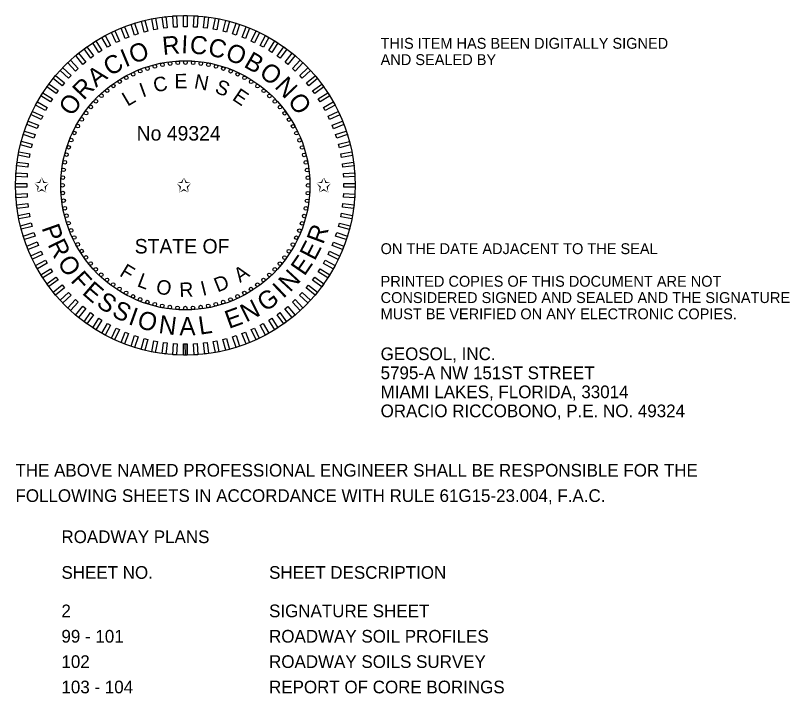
# Model space of a CAD drawing. Extents: x -816.9 to -790.1, y -2199.5 to -2188.9.
# Drawn here: x -794.327 to -790.055, y -2192.952 to -2189.209 of the extents above; entities that cross this region are included whole.
import ezdxf

# ---------------------------------------------------------------- set-up
doc = ezdxf.new("R2010")
doc.units = 0
for name, color, linetype in [('Logo_dp', 7, 'Continuous'), ('NonPlottingEle_dp', 7, 'Continuous'), ('TextMisc', 7, 'Continuous'), ('TextNotes', 7, 'Continuous')]:
    doc.layers.add(name, color=color, linetype=linetype)

msp = doc.modelspace()

# ---------------------------------------------------------------- linework, layer by layer
at = {"layer": 'Logo_dp'}
for p, q in [((-793.3999, -2191.0843), (-793.4001, -2191.0218)), ((-793.3899, -2191.0843), (-793.3901, -2191.0218)), ((-793.3799, -2191.0843), (-793.3801, -2191.0218))]:
    msp.add_line(p, q, dxfattribs=at)
for points in [[(-793.5976, -2189.2967), (-793.6172, -2189.3018), (-793.6327, -2189.2413), (-793.6132, -2189.2363)], [(-793.5438, -2189.2854), (-793.5637, -2189.2892), (-793.5754, -2189.2278), (-793.5555, -2189.224)], [(-793.4895, -2189.2774), (-793.5095, -2189.2799), (-793.5173, -2189.218), (-793.4973, -2189.2155)], [(-793.4347, -2189.2729), (-793.4548, -2189.2741), (-793.4587, -2189.2118), (-793.4386, -2189.2106)], [(-793.3797, -2189.2718), (-793.3999, -2189.2718), (-793.3999, -2189.2093), (-793.3797, -2189.2093)], [(-793.3248, -2189.2741), (-793.3449, -2189.2729), (-793.341, -2189.2106), (-793.3209, -2189.2118)], [(-793.2701, -2189.28), (-793.2901, -2189.2774), (-793.2823, -2189.2155), (-793.2623, -2189.218)], [(-793.2159, -2189.2892), (-793.2357, -2189.2854), (-793.224, -2189.2241), (-793.2042, -2189.2279)], [(-793.1624, -2189.3018), (-793.182, -2189.2968), (-793.1664, -2189.2363), (-793.1469, -2189.2413)], [(-793.7025, -2189.3295), (-793.7213, -2189.3369), (-793.7443, -2189.2789), (-793.7255, -2189.2714)], [(-793.6506, -2189.3115), (-793.6698, -2189.3177), (-793.6891, -2189.2583), (-793.6699, -2189.2521)], [(-793.1098, -2189.3178), (-793.129, -2189.3115), (-793.1097, -2189.2521), (-793.0905, -2189.2584)], [(-793.0583, -2189.337), (-793.0771, -2189.3295), (-793.0541, -2189.2715), (-793.0353, -2189.2789)], [(-793.8025, -2189.3751), (-793.8202, -2189.3848), (-793.8503, -2189.3301), (-793.8326, -2189.3204)], [(-793.7532, -2189.3507), (-793.7715, -2189.3593), (-793.7981, -2189.3028), (-793.7798, -2189.2942)], [(-793.0081, -2189.3594), (-793.0264, -2189.3508), (-792.9998, -2189.2943), (-792.9815, -2189.3029)], [(-792.9594, -2189.3849), (-792.9771, -2189.3752), (-792.947, -2189.3205), (-792.9293, -2189.3302)], [(-793.8502, -2189.4025), (-793.8672, -2189.4134), (-793.9007, -2189.3606), (-793.8836, -2189.3498)], [(-792.9124, -2189.4135), (-792.9295, -2189.4026), (-792.896, -2189.3499), (-792.879, -2189.3607)], [(-793.896, -2189.4329), (-793.9123, -2189.4448), (-793.949, -2189.3943), (-793.9327, -2189.3824)], [(-792.8673, -2189.4449), (-792.8836, -2189.433), (-792.8469, -2189.3825), (-792.8306, -2189.3944)], [(-793.9815, -2189.502), (-793.9962, -2189.5158), (-794.0389, -2189.4703), (-794.0242, -2189.4565)], [(-793.9398, -2189.4661), (-793.9554, -2189.479), (-793.9952, -2189.4309), (-793.9796, -2189.418)], [(-792.8243, -2189.4791), (-792.8398, -2189.4662), (-792.8, -2189.4181), (-792.7845, -2189.431)], [(-792.7835, -2189.5159), (-792.7982, -2189.5021), (-792.7554, -2189.4566), (-792.7407, -2189.4704)], [(-794.0208, -2189.5404), (-794.0346, -2189.5551), (-794.0801, -2189.5124), (-794.0663, -2189.4976)], [(-792.745, -2189.5552), (-792.7589, -2189.5405), (-792.7133, -2189.4978), (-792.6995, -2189.5125)], [(-794.0576, -2189.5812), (-794.0705, -2189.5968), (-794.1186, -2189.5569), (-794.1057, -2189.5414)], [(-792.7092, -2189.5969), (-792.722, -2189.5813), (-792.6739, -2189.5415), (-792.6611, -2189.5571)], [(-794.0918, -2189.6242), (-794.1037, -2189.6406), (-794.1542, -2189.6039), (-794.1423, -2189.5875)], [(-792.676, -2189.6407), (-792.6878, -2189.6244), (-792.6373, -2189.5877), (-792.6255, -2189.604)], [(-794.1232, -2189.6693), (-794.1341, -2189.6864), (-794.1868, -2189.6529), (-794.176, -2189.6359)], [(-792.6456, -2189.6865), (-792.6564, -2189.6695), (-792.6037, -2189.636), (-792.5929, -2189.6531)], [(-794.1518, -2189.7163), (-794.1615, -2189.734), (-794.2162, -2189.7039), (-794.2065, -2189.6863)], [(-792.6182, -2189.7342), (-792.6279, -2189.7165), (-792.5732, -2189.6864), (-792.5635, -2189.7041)], [(-794.1773, -2189.765), (-794.1859, -2189.7833), (-794.2424, -2189.7567), (-794.2338, -2189.7384)], [(-792.5938, -2189.7835), (-792.6024, -2189.7652), (-792.5459, -2189.7386), (-792.5373, -2189.7569)], [(-794.1997, -2189.8152), (-794.2071, -2189.834), (-794.2652, -2189.811), (-794.2578, -2189.7922)], [(-792.5726, -2189.8342), (-792.58, -2189.8154), (-792.5219, -2189.7924), (-792.5145, -2189.8112)], [(-794.2189, -2189.8667), (-794.2252, -2189.8859), (-794.2846, -2189.8666), (-794.2783, -2189.8474)], [(-792.5545, -2189.8861), (-792.5608, -2189.8669), (-792.5014, -2189.8476), (-792.4952, -2189.8668)], [(-794.2349, -2189.9193), (-794.2399, -2189.9389), (-794.3004, -2189.9234), (-794.2954, -2189.9038)], [(-792.5398, -2189.9391), (-792.5448, -2189.9195), (-792.4844, -2189.904), (-792.4793, -2189.9235)], [(-794.2475, -2189.9728), (-794.2513, -2189.9927), (-794.3126, -2189.981), (-794.3088, -2189.9611)], [(-792.5284, -2189.9929), (-792.5322, -2189.973), (-792.4709, -2189.9613), (-792.4671, -2189.9812)], [(-794.2567, -2190.027), (-794.2593, -2190.0471), (-794.3212, -2190.0392), (-794.3187, -2190.0192)], [(-792.5205, -2190.0472), (-792.523, -2190.0272), (-792.4611, -2190.0194), (-792.4585, -2190.0394)], [(-794.2626, -2190.0817), (-794.2638, -2190.1018), (-794.3261, -2190.0979), (-794.3249, -2190.0778)], [(-792.5159, -2190.102), (-792.5172, -2190.0819), (-792.4549, -2190.078), (-792.4536, -2190.0981)], [(-794.2649, -2190.1366), (-794.2649, -2190.1568), (-794.3274, -2190.1568), (-794.3274, -2190.1366)], [(-792.5149, -2190.157), (-792.5149, -2190.1368), (-792.4524, -2190.1368), (-792.4524, -2190.157)], [(-794.2638, -2190.1916), (-794.2626, -2190.2117), (-794.3249, -2190.2157), (-794.3261, -2190.1955)], [(-792.5172, -2190.2119), (-792.516, -2190.1918), (-792.4536, -2190.1957), (-792.4549, -2190.2158)], [(-794.2593, -2190.2464), (-794.2568, -2190.2664), (-794.3187, -2190.2742), (-794.3212, -2190.2542)], [(-792.523, -2190.2666), (-792.5205, -2190.2466), (-792.4586, -2190.2544), (-792.4611, -2190.2744)], [(-794.2513, -2190.3008), (-794.2475, -2190.3206), (-794.3089, -2190.3323), (-794.3127, -2190.3125)], [(-792.5323, -2190.3208), (-792.5285, -2190.301), (-792.4671, -2190.3127), (-792.4709, -2190.3325)], [(-794.24, -2190.3546), (-794.2349, -2190.3741), (-794.2954, -2190.3896), (-794.3004, -2190.3701)], [(-792.5449, -2190.3743), (-792.5399, -2190.3547), (-792.4794, -2190.3703), (-792.4844, -2190.3898)], [(-794.2252, -2190.4075), (-794.219, -2190.4267), (-794.2784, -2190.446), (-794.2846, -2190.4268)], [(-792.5608, -2190.4269), (-792.5546, -2190.4077), (-792.4952, -2190.427), (-792.5014, -2190.4462)], [(-794.2072, -2190.4595), (-794.1998, -2190.4782), (-794.2578, -2190.5012), (-794.2653, -2190.4824)], [(-792.5801, -2190.4784), (-792.5726, -2190.4596), (-792.5146, -2190.4826), (-792.522, -2190.5014)], [(-794.186, -2190.5102), (-794.1774, -2190.5284), (-794.2339, -2190.555), (-794.2425, -2190.5367)], [(-792.6025, -2190.5286), (-792.5939, -2190.5103), (-792.5374, -2190.5369), (-792.546, -2190.5552)], [(-794.1616, -2190.5594), (-794.1519, -2190.5771), (-794.2066, -2190.6072), (-794.2163, -2190.5895)], [(-792.628, -2190.5773), (-792.6183, -2190.5596), (-792.5636, -2190.5897), (-792.5733, -2190.6074)], [(-794.1342, -2190.6071), (-794.1233, -2190.6241), (-794.1761, -2190.6576), (-794.1869, -2190.6405)], [(-792.6565, -2190.6243), (-792.6457, -2190.6072), (-792.593, -2190.6407), (-792.6038, -2190.6577)], [(-794.1038, -2190.6529), (-794.0919, -2190.6692), (-794.1424, -2190.7059), (-794.1543, -2190.6896)], [(-792.688, -2190.6694), (-792.6761, -2190.653), (-792.6256, -2190.6898), (-792.6374, -2190.7061)], [(-794.0706, -2190.6967), (-794.0577, -2190.7123), (-794.1058, -2190.7521), (-794.1187, -2190.7365)], [(-794.0347, -2190.7384), (-794.0209, -2190.7531), (-794.0664, -2190.7958), (-794.0802, -2190.7811)], [(-792.759, -2190.7532), (-792.7452, -2190.7385), (-792.6997, -2190.7813), (-792.7135, -2190.796)], [(-792.7222, -2190.7124), (-792.7093, -2190.6969), (-792.6612, -2190.7367), (-792.674, -2190.7522)], [(-793.9963, -2190.7777), (-793.9816, -2190.7915), (-794.0243, -2190.837), (-794.0391, -2190.8232)], [(-792.7983, -2190.7917), (-792.7836, -2190.7778), (-792.7409, -2190.8234), (-792.7556, -2190.8372)], [(-793.9555, -2190.8145), (-793.9399, -2190.8274), (-793.9797, -2190.8755), (-793.9953, -2190.8627)], [(-792.84, -2190.8275), (-792.8244, -2190.8147), (-792.7846, -2190.8628), (-792.8002, -2190.8756)], [(-793.9125, -2190.8487), (-793.8961, -2190.8606), (-793.9328, -2190.9111), (-793.9492, -2190.8993)], [(-792.8838, -2190.8607), (-792.8675, -2190.8488), (-792.8308, -2190.8994), (-792.8471, -2190.9112)], [(-793.8674, -2190.8802), (-793.8503, -2190.891), (-793.8838, -2190.9437), (-793.9008, -2190.9329)], [(-793.8204, -2190.9087), (-793.8027, -2190.9184), (-793.8328, -2190.9731), (-793.8504, -2190.9634)], [(-792.9773, -2190.9185), (-792.9596, -2190.9088), (-792.9295, -2190.9635), (-792.9472, -2190.9732)], [(-792.9296, -2190.8911), (-792.9126, -2190.8803), (-792.8791, -2190.933), (-792.8962, -2190.9438)], [(-793.7717, -2190.9342), (-793.7534, -2190.9428), (-793.78, -2190.9993), (-793.7983, -2190.9907)], [(-793.0265, -2190.9429), (-793.0083, -2190.9343), (-792.9817, -2190.9908), (-792.9999, -2190.9994)], [(-793.7215, -2190.9566), (-793.7027, -2190.9641), (-793.7257, -2191.0221), (-793.7445, -2191.0147)], [(-793.67, -2190.9759), (-793.6508, -2190.9821), (-793.6701, -2191.0415), (-793.6893, -2191.0352)], [(-793.6174, -2190.9918), (-793.5978, -2190.9968), (-793.6133, -2191.0573), (-793.6329, -2191.0523)], [(-793.1821, -2190.9969), (-793.1626, -2190.9919), (-793.1471, -2191.0523), (-793.1666, -2191.0574)], [(-793.1292, -2190.9822), (-793.11, -2190.9759), (-793.0907, -2191.0353), (-793.1099, -2191.0415)], [(-793.0772, -2190.9641), (-793.0585, -2190.9567), (-793.0355, -2191.0148), (-793.0543, -2191.0222)], [(-793.5639, -2191.0044), (-793.544, -2191.0082), (-793.5557, -2191.0695), (-793.5756, -2191.0658)], [(-793.5097, -2191.0137), (-793.4896, -2191.0162), (-793.4975, -2191.0781), (-793.5175, -2191.0756)], [(-793.455, -2191.0195), (-793.4348, -2191.0207), (-793.4388, -2191.0831), (-793.4589, -2191.0818)], [(-793.4001, -2191.0218), (-793.3799, -2191.0218), (-793.3799, -2191.0843), (-793.4001, -2191.0843)], [(-793.3451, -2191.0208), (-793.325, -2191.0195), (-793.321, -2191.0818), (-793.3412, -2191.0831)], [(-793.2903, -2191.0162), (-793.2703, -2191.0137), (-793.2625, -2191.0756), (-793.2825, -2191.0782)], [(-793.2359, -2191.0082), (-793.2161, -2191.0045), (-793.2044, -2191.0658), (-793.2242, -2191.0696)]]:
    msp.add_lwpolyline(points, close=True, dxfattribs=at)
for centre in [(-793.5987, -2189.5023), (-793.5578, -2189.4905), (-793.5163, -2189.4812), (-793.4742, -2189.4746), (-793.4319, -2189.4706), (-793.3893, -2189.4693), (-793.3468, -2189.4707), (-793.3044, -2189.4748), (-793.2624, -2189.4814), (-793.2209, -2189.4908), (-793.18, -2189.5027), (-793.7158, -2189.5529), (-793.6778, -2189.5336), (-793.6388, -2189.5167), (-793.14, -2189.5171), (-793.1009, -2189.5341), (-793.7524, -2189.5745), (-793.063, -2189.5534), (-793.0264, -2189.5751), (-793.8213, -2189.6245), (-793.7876, -2189.5984), (-792.9912, -2189.5991), (-792.9576, -2189.6252), (-793.8532, -2189.6526), (-792.9257, -2189.6533), (-793.9115, -2189.7145), (-793.8834, -2189.6826), (-792.8956, -2189.6835), (-792.8675, -2189.7154), (-793.9376, -2189.7481), (-792.8415, -2189.7491), (-793.9616, -2189.7833), (-792.8176, -2189.7843), (-793.9833, -2189.8199), (-792.7959, -2189.8209), (-794.0026, -2189.8578), (-792.7767, -2189.8589), (-794.034, -2189.9369), (-794.0196, -2189.8969), (-792.7598, -2189.8979), (-794.0459, -2189.9778), (-792.7454, -2189.938), (-792.7336, -2189.9789), (-794.0552, -2190.0193), (-792.7243, -2190.0204), (-794.0619, -2190.0613), (-792.7177, -2190.0625), (-794.066, -2190.1037), (-792.7137, -2190.1048), (-794.0674, -2190.1462), (-792.7124, -2190.1474), (-794.0661, -2190.1888), (-792.7138, -2190.1899), (-794.0621, -2190.2312), (-792.7178, -2190.2323), (-794.0555, -2190.2732), (-792.7245, -2190.2743), (-794.0462, -2190.3147), (-792.7338, -2190.3158), (-794.0344, -2190.3556), (-792.7457, -2190.3567), (-794.02, -2190.3957), (-792.7602, -2190.3967), (-794.0031, -2190.4348), (-792.7771, -2190.4358), (-793.9838, -2190.4727), (-792.7965, -2190.4737), (-793.9622, -2190.5093), (-792.8182, -2190.5103), (-793.9383, -2190.5446), (-793.9122, -2190.5782), (-792.8421, -2190.5455), (-793.8841, -2190.6102), (-792.8964, -2190.611), (-792.8682, -2190.5791), (-793.8541, -2190.6403), (-792.9265, -2190.641), (-793.8222, -2190.6684), (-793.7885, -2190.6946), (-792.9921, -2190.6952), (-792.9585, -2190.6692), (-793.7534, -2190.7185), (-793.7168, -2190.7402), (-793.064, -2190.7408), (-793.0274, -2190.7191), (-793.6788, -2190.7596), (-793.6398, -2190.7765), (-793.5998, -2190.7909), (-793.1811, -2190.7913), (-793.141, -2190.7769), (-793.1019, -2190.76), (-793.5589, -2190.8029), (-793.5174, -2190.8122), (-793.4754, -2190.8189), (-793.433, -2190.8229), (-793.3899, -2190.8243), (-793.3479, -2190.823), (-793.3055, -2190.819), (-793.2635, -2190.8124), (-793.222, -2190.8031)]:
    msp.add_circle(centre, 0.01, dxfattribs=at)
at = {"layer": 'NonPlottingEle_dp'}
for radius in [0.9375, 0.6875]:
    msp.add_circle((-793.3899, -2190.1468), radius, dxfattribs=at)

# ---------------------------------------------------------------- texts
at = {"layer": 'Logo_dp'}
for s, height, rotation, p in [('R', 0.1, 5.3723, (-793.5127, -2189.4277)), ('I', 0.1, 357.5509, (-793.4137, -2189.4176)), ('C', 0.1, 354.0177, (-793.3688, -2189.4175)), ('O', 0.1, 19.1125, (-793.68, -2189.4774)), ('C', 0.1, 346.2809, (-793.2708, -2189.427)), ('O', 0.1, 338.5441, (-793.175, -2189.4496)), ('I', 0.1, 22.6457, (-793.7207, -2189.4966)), ('B', 0.1, 329.8833, (-793.0724, -2189.4899)), ('C', 0.1, 30.3825, (-793.8053, -2189.547)), ('A', 0.1, 38.1495, (-793.8825, -2189.6087)), ('O', 0.1, 322.2793, (-792.9883, -2189.5377)), ('E', 0.08, 0.4186, (-793.4496, -2189.6117)), ('N', 0.08, 349.2914, (-793.3452, -2189.6103)), ('R', 0.1, 45.9708, (-793.9512, -2189.6807)), ('I', 0.08, 20.0117, (-793.6256, -2189.6627)), ('C', 0.08, 12.2025, (-793.5576, -2189.6352)), ('S', 0.08, 337.0221, (-793.2322, -2189.632)), ('N', 0.1, 313.6185, (-792.9011, -2189.6051)), ('E', 0.08, 325.8663, (-793.1356, -2189.6722)), ('O', 0.1, 54.6317, (-794.015, -2189.7705)), ('L', 0.08, 30.4021, (-793.709, -2189.7132)), ('O', 0.1, 305.3683, (-792.8285, -2189.6809)), ('P', 0.1, 289.4055, (-794.1846, -2190.3814)), ('R', 0.1, 69.5134, (-792.6297, -2190.4765)), ('R', 0.1, 296.1458, (-794.1516, -2190.473)), ('E', 0.1, 62.4712, (-792.6759, -2190.5672)), ('O', 0.1, 303.9671, (-794.1001, -2190.5737)), ('E', 0.1, 55.4289, (-792.7328, -2190.6516)), ('F', 0.08, 328.7241, (-793.7579, -2190.6434)), ('A', 0.08, 34.4992, (-793.088, -2190.6862)), ('N', 0.1, 47.1788, (-792.812, -2190.7407)), ('F', 0.1, 312.628, (-794.0277, -2190.6757)), ('L', 0.08, 339.2916, (-793.6606, -2190.7025)), ('D', 0.08, 22.0128, (-793.2118, -2190.7387)), ('E', 0.1, 319.0783, (-793.9643, -2190.744)), ('O', 0.08, 349.6821, (-793.556, -2190.7422)), ('R', 0.08, 2.3398, (-793.4215, -2190.7641)), ('I', 0.08, 14.2037, (-793.2939, -2190.7574)), ('I', 0.1, 43.6456, (-792.8497, -2190.7751)), ('G', 0.1, 35.1115, (-792.9489, -2190.8483)), ('S', 0.1, 326.1206, (-793.8867, -2190.81)), ('N', 0.1, 26.8614, (-793.0542, -2190.9044)), ('S', 0.1, 333.193, (-793.8013, -2190.8661)), ('I', 0.1, 340.2654, (-793.7096, -2190.9113)), ('E', 0.1, 19.8191, (-793.1496, -2190.9398)), ('O', 0.1, 343.7986, (-793.6619, -2190.9295)), ('N', 0.1, 352.4595, (-793.5409, -2190.9615)), ('A', 0.1, 0.7097, (-793.4224, -2190.9748)), ('L', 0.1, 8.4767, (-793.3102, -2190.9716))]:
    msp.add_text(s, height=height, rotation=rotation, dxfattribs=at).set_placement(p)
for s, p in [('No 49324', (-793.6588, -2189.8996)), ('✩', (-794.2249, -2190.1848)), ('✩', (-793.4401, -2190.1848)), ('✩', (-792.6683, -2190.1848)), ('STATE OF', (-793.6696, -2190.523))]:
    msp.add_text(s, height=0.08, dxfattribs=at).set_placement(p)
at = {"layer": 'TextMisc'}
for s, height, p in [('THIS ITEM HAS BEEN DIGITALLY SIGNED ', 0.06, (-792.3122, -2189.393)), ('AND SEALED BY', 0.06, (-792.3122, -2189.483)), ('ON THE DATE ADJACENT TO THE SEAL', 0.06, (-792.3122, -2190.5264)), ('PRINTED COPIES OF THIS DOCUMENT ARE NOT ', 0.06, (-792.3122, -2190.7064)), ('CONSIDERED SIGNED AND SEALED AND THE SIGNATURE ', 0.06, (-792.3122, -2190.7964)), ('MUST BE VERIFIED ON ANY ELECTRONIC COPIES.', 0.06, (-792.3122, -2190.8864)), ('GEOSOL, INC.', 0.07, (-792.3122, -2191.1116)), ('5795-A NW 151ST STREET', 0.07, (-792.3122, -2191.2166)), ('MIAMI LAKES, FLORIDA, 33014', 0.07, (-792.3122, -2191.3216)), ('ORACIO RICCOBONO, P.E. NO. 49324', 0.07, (-792.3122, -2191.4266)), ('THE ABOVE NAMED PROFESSIONAL ENGINEER SHALL BE RESPONSIBLE FOR THE ', 0.07, (-794.3274, -2191.7544)), ('FOLLOWING SHEETS IN ACCORDANCE WITH RULE 61G15-23.004, F.A.C.', 0.07, (-794.3274, -2191.8944)), ('ROADWAY PLANS', 0.07, (-794.0737, -2192.1214))]:
    msp.add_text(s, height=height, dxfattribs=at).set_placement(p)
at = {"layer": 'TextNotes'}
for s, p in [('SHEET NO.', (-794.0737, -2192.3184)), ('SHEET DESCRIPTION', (-792.9278, -2192.3184)), ('2', (-794.0737, -2192.5306)), ('SIGNATURE SHEET', (-792.9278, -2192.5306)), ('99 - 101', (-794.0737, -2192.6706)), ('ROADWAY SOIL PROFILES', (-792.9278, -2192.6706)), ('102', (-794.0737, -2192.8106)), ('ROADWAY SOILS SURVEY', (-792.9278, -2192.8106)), ('103 - 104', (-794.0737, -2192.9506)), ('REPORT OF CORE BORINGS', (-792.9278, -2192.9506))]:
    msp.add_text(s, height=0.07, dxfattribs=at).set_placement(p)

doc.saveas('drawing.dxf')
